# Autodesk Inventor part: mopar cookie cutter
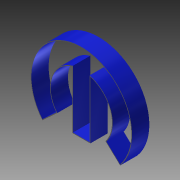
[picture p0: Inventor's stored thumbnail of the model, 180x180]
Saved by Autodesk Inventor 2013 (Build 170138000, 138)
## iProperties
Created: 2015-02
Part Number: mopar cookie cutter
Material: Generic
Document SubType Name: Modeling
Designer: 1763099
Density: 1 g/cm^3
Author: 1763099
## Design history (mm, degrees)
sketch "Sketch1"
  geometry: L1 (58.478, -153.12)-(25.625, -183.413); L2 (91.356, -47.734)-(91.356, -174.706); L3 (131.232, -47.594)-(131.232, -174.706); L4 (91.356, -174.706)-(131.232, -174.706); L5 (164.557, -153.636)-(197.034, -183.959); L6 (25.781, -181.186)-(56.403, -152.949); L7 (92.888, -45.703)-(92.888, -173.174); L8 (92.888, -173.174)-(129.7, -173.174); L9 (129.7, -173.174)-(129.7, -45.572); L10 (166.627, -153.473)-(196.892, -181.731); A1 r 66.701 centre (110.664, -111.58) between (91.356, -47.734) and (58.478, -153.12); A2 r 67.037 centre (112.135, -111.853) between (164.557, -153.636) and (131.232, -47.594); A3 r 111.737 centre (111.558, -111.995) between (197.034, -183.959) and (25.625, -183.413); A4 r 68.233 centre (110.664, -111.58) between (92.888, -45.703) and (56.403, -152.949); A5 r 68.569 centre (112.135, -111.853) between (166.627, -153.473) and (129.7, -45.572); A6 r 110.205 centre (111.558, -111.995) between (196.892, -181.731) and (25.781, -181.186); 1 further point
  constraints: 20 end point, 12 point on circle, 6 centre point, 2 parallel, 2 perpendicular, 7 other
extrude "Extrusion1" new body sketch "Sketch1" distance "d3" = 38.1; taper "d4" = 0 deg
body "Solid1"
